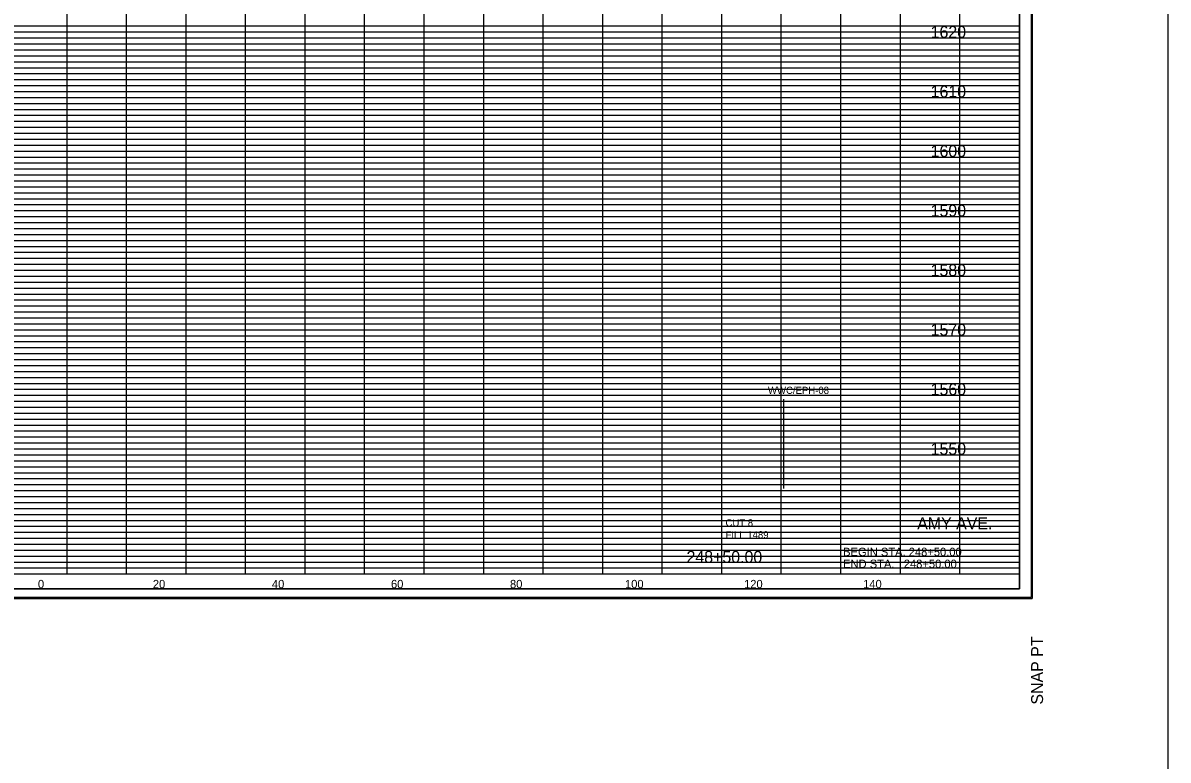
# Model space of a CAD drawing. Extents: x 955 to 1375, y 1248 to 3657.
# Drawn here: x 1152.6 to 1345, y 2858.7 to 2982.5 of the extents above; entities that cross this region are included whole.
import ezdxf

# ---------------------------------------------------------------- set-up
doc = ezdxf.new("R2010")
doc.units = 0
for name, color, linetype in [('DESIGN - SHEET - Corner Text', 7, 'Continuous'), ('DESIGN - SHEET - Light Grid', 7, 'Continuous'), ('DESIGN - SHEET - Linework', 7, 'Continuous'), ('DESIGN - SHEET - Plot Shape', 7, 'Continuous'), ('DESIGN - TYPICAL - Text', 7, 'Continuous'), ('DESIGN - UTILITIES - Cable (Overhead) with Text', 7, 'Continuous'), ('SURVEY - NON-TRANSPORTATION - Features', 7, 'Continuous'), ('SURVEY - NON-TRANSPORTATION - Features Text', 7, 'Continuous')]:
    doc.layers.add(name, color=color, linetype=linetype)

# ---------------------------------------------------------------- blocks, each defined once
blk = doc.blocks.new('XSTSHT')
at = {"layer": 'DESIGN - SHEET - Light Grid'}
for p, q in [((8, 9.2), (16, 9.2)), ((8, 9.1), (16, 9.1)), ((16, 9.2), (24, 9.2)), ((16, 9.1), (24, 9.1)), ((24, 9.2), (32, 9.2)), ((24, 9.1), (32, 9.1)), ((8, 8.9), (16, 8.9)), ((16, 8.9), (24, 8.9)), ((24, 8.9), (32, 8.9)), ((8, 8.8), (16, 8.8)), ((8, 8.7), (16, 8.7)), ((16, 8.8), (24, 8.8)), ((16, 8.7), (24, 8.7)), ((24, 8.8), (32, 8.8)), ((24, 8.7), (32, 8.7)), ((8, 8.6), (16, 8.6)), ((8, 8.5), (16, 8.5)), ((16, 8.6), (24, 8.6)), ((16, 8.5), (24, 8.5)), ((24, 8.6), (32, 8.6)), ((24, 8.5), (32, 8.5)), ((8, 8.4), (16, 8.4)), ((8, 8.3), (16, 8.3)), ((16, 8.4), (24, 8.4)), ((16, 8.3), (24, 8.3)), ((24, 8.4), (32, 8.4)), ((24, 8.3), (32, 8.3)), ((8, 8.2), (16, 8.2)), ((8, 8.1), (16, 8.1)), ((16, 8.2), (24, 8.2)), ((16, 8.1), (24, 8.1)), ((24, 8.2), (32, 8.2)), ((24, 8.1), (32, 8.1)), ((8, 7.9), (16, 7.9)), ((16, 7.9), (24, 7.9)), ((24, 7.9), (32, 7.9)), ((8, 7.8), (16, 7.8)), ((8, 7.7), (16, 7.7)), ((16, 7.8), (24, 7.8)), ((16, 7.7), (24, 7.7)), ((24, 7.8), (32, 7.8)), ((24, 7.7), (32, 7.7)), ((8, 7.6), (16, 7.6)), ((16, 7.6), (24, 7.6)), ((24, 7.6), (32, 7.6)), ((8, 7.5), (16, 7.5)), ((8, 7.4), (16, 7.4)), ((16, 7.5), (24, 7.5)), ((16, 7.4), (24, 7.4)), ((24, 7.5), (32, 7.5)), ((24, 7.4), (32, 7.4)), ((8, 7.3), (16, 7.3)), ((8, 7.2), (16, 7.2)), ((16, 7.3), (24, 7.3)), ((16, 7.2), (24, 7.2)), ((24, 7.3), (32, 7.3)), ((24, 7.2), (32, 7.2)), ((8, 7.1), (16, 7.1)), ((16, 7.1), (24, 7.1)), ((24, 7.1), (32, 7.1)), ((8, 6.9), (16, 6.9)), ((8, 6.8), (16, 6.8)), ((16, 6.9), (24, 6.9)), ((16, 6.8), (24, 6.8)), ((24, 6.9), (32, 6.9)), ((24, 6.8), (32, 6.8)), ((8, 6.7), (16, 6.7)), ((8, 6.6), (16, 6.6)), ((16, 6.7), (24, 6.7)), ((16, 6.6), (24, 6.6)), ((24, 6.7), (32, 6.7)), ((24, 6.6), (32, 6.6)), ((8, 6.5), (16, 6.5)), ((8, 6.4), (16, 6.4)), ((16, 6.5), (24, 6.5)), ((16, 6.4), (24, 6.4)), ((24, 6.5), (32, 6.5)), ((24, 6.4), (32, 6.4)), ((8, 6.3), (16, 6.3)), ((8, 6.2), (16, 6.2)), ((16, 6.3), (24, 6.3)), ((16, 6.2), (24, 6.2)), ((24, 6.3), (32, 6.3)), ((24, 6.2), (32, 6.2)), ((8, 6.1), (16, 6.1)), ((16, 6.1), (24, 6.1)), ((24, 6.1), (32, 6.1)), ((8, 5.9), (16, 5.9)), ((8, 5.8), (16, 5.8)), ((16, 5.9), (24, 5.9)), ((16, 5.8), (24, 5.8)), ((24, 5.9), (32, 5.9)), ((24, 5.8), (32, 5.8)), ((8, 5.7), (16, 5.7)), ((8, 5.6), (16, 5.6)), ((16, 5.7), (24, 5.7)), ((16, 5.6), (24, 5.6)), ((24, 5.7), (32, 5.7)), ((24, 5.6), (32, 5.6)), ((8, 5.5), (16, 5.5)), ((8, 5.4), (16, 5.4)), ((16, 5.5), (24, 5.5)), ((16, 5.4), (24, 5.4)), ((24, 5.5), (32, 5.5)), ((24, 5.4), (32, 5.4)), ((8, 5.3), (16, 5.3)), ((8, 5.2), (16, 5.2)), ((16, 5.3), (24, 5.3)), ((16, 5.2), (24, 5.2)), ((24, 5.3), (32, 5.3)), ((24, 5.2), (32, 5.2)), ((8, 5.1), (16, 5.1)), ((16, 5.1), (24, 5.1)), ((24, 5.1), (32, 5.1)), ((8, 4.9), (16, 4.9)), ((16, 4.9), (24, 4.9)), ((24, 4.9), (32, 4.9)), ((8, 4.8), (16, 4.8)), ((8, 4.7), (16, 4.7)), ((16, 4.8), (24, 4.8)), ((16, 4.7), (24, 4.7)), ((24, 4.8), (32, 4.8)), ((24, 4.7), (32, 4.7)), ((8, 4.6), (16, 4.6)), ((8, 4.5), (16, 4.5)), ((16, 4.6), (24, 4.6)), ((16, 4.5), (24, 4.5)), ((24, 4.6), (32, 4.6)), ((24, 4.5), (32, 4.5)), ((8, 4.4), (16, 4.4)), ((8, 4.3), (16, 4.3)), ((16, 4.4), (24, 4.4)), ((16, 4.3), (24, 4.3)), ((24, 4.4), (32, 4.4)), ((24, 4.3), (32, 4.3)), ((8, 4.2), (16, 4.2)), ((8, 4.1), (16, 4.1)), ((16, 4.2), (24, 4.2)), ((16, 4.1), (24, 4.1)), ((24, 4.2), (32, 4.2)), ((24, 4.1), (32, 4.1)), ((8, 3.9), (16, 3.9)), ((16, 3.9), (24, 3.9)), ((24, 3.9), (32, 3.9)), ((8, 3.8), (16, 3.8)), ((8, 3.7), (16, 3.7)), ((16, 3.8), (24, 3.8)), ((16, 3.7), (24, 3.7)), ((24, 3.8), (32, 3.8)), ((24, 3.7), (32, 3.7)), ((8, 3.6), (16, 3.6)), ((8, 3.5), (16, 3.5)), ((16, 3.6), (24, 3.6)), ((16, 3.5), (24, 3.5)), ((24, 3.6), (32, 3.6)), ((24, 3.5), (32, 3.5)), ((8, 3.4), (16, 3.4)), ((8, 3.3), (16, 3.3)), ((16, 3.4), (24, 3.4)), ((16, 3.3), (24, 3.3)), ((24, 3.4), (32, 3.4)), ((24, 3.3), (32, 3.3)), ((8, 3.2), (16, 3.2)), ((8, 3.1), (16, 3.1)), ((16, 3.2), (24, 3.2)), ((16, 3.1), (24, 3.1)), ((24, 3.2), (32, 3.2)), ((24, 3.1), (32, 3.1)), ((8, 2.9), (16, 2.9)), ((16, 2.9), (24, 2.9)), ((24, 2.9), (32, 2.9)), ((8, 2.8), (16, 2.8)), ((8, 2.7), (16, 2.7)), ((16, 2.8), (24, 2.8)), ((16, 2.7), (24, 2.7)), ((24, 2.8), (32, 2.8)), ((24, 2.7), (32, 2.7)), ((8, 2.6), (16, 2.6)), ((16, 2.6), (24, 2.6)), ((24, 2.6), (32, 2.6)), ((8, 2.5), (16, 2.5)), ((8, 2.4), (16, 2.4)), ((16, 2.5), (24, 2.5)), ((16, 2.4), (24, 2.4)), ((24, 2.5), (32, 2.5)), ((24, 2.4), (32, 2.4)), ((8, 2.3), (16, 2.3)), ((8, 2.2), (16, 2.2)), ((16, 2.3), (24, 2.3)), ((16, 2.2), (24, 2.2)), ((24, 2.3), (32, 2.3)), ((24, 2.2), (32, 2.2)), ((8, 2.1), (16, 2.1)), ((16, 2.1), (24, 2.1)), ((24, 2.1), (32, 2.1)), ((8, 1.9), (16, 1.9)), ((8, 1.8), (16, 1.8)), ((16, 1.9), (24, 1.9)), ((16, 1.8), (24, 1.8)), ((24, 1.9), (32, 1.9)), ((24, 1.8), (32, 1.8)), ((8, 1.7), (16, 1.7)), ((8, 1.6), (16, 1.6)), ((16, 1.7), (24, 1.7)), ((16, 1.6), (24, 1.6)), ((24, 1.7), (32, 1.7)), ((24, 1.6), (32, 1.6)), ((8, 1.5), (16, 1.5)), ((8, 1.4), (16, 1.4)), ((16, 1.5), (24, 1.5)), ((16, 1.4), (24, 1.4)), ((24, 1.5), (32, 1.5)), ((24, 1.4), (32, 1.4)), ((8, 1.3), (16, 1.3)), ((8, 1.2), (16, 1.2)), ((16, 1.3), (24, 1.3)), ((16, 1.2), (24, 1.2)), ((24, 1.3), (32, 1.3)), ((24, 1.2), (32, 1.2)), ((8, 1.1), (16, 1.1)), ((16, 1.1), (24, 1.1)), ((24, 1.1), (32, 1.1)), ((8, 0.9), (16, 0.9)), ((8, 0.8), (16, 0.8)), ((16, 0.9), (24, 0.9)), ((16, 0.8), (24, 0.8)), ((24, 0.9), (32, 0.9)), ((24, 0.8), (32, 0.8)), ((8, 0.7), (16, 0.7)), ((8, 0.6), (16, 0.6)), ((16, 0.7), (24, 0.7)), ((16, 0.6), (24, 0.6)), ((24, 0.7), (32, 0.7)), ((24, 0.6), (32, 0.6)), ((8, 0.5), (16, 0.5)), ((8, 0.4), (16, 0.4)), ((16, 0.5), (24, 0.5)), ((16, 0.4), (24, 0.4)), ((24, 0.5), (32, 0.5)), ((24, 0.4), (32, 0.4)), ((8, 0.3), (16, 0.3)), ((8, 0.2), (16, 0.2)), ((16, 0.3), (24, 0.3)), ((16, 0.2), (24, 0.2)), ((24, 0.3), (32, 0.3)), ((24, 0.2), (32, 0.2)), ((8, 0.1), (16, 0.1)), ((16, 0.1), (24, 0.1)), ((24, 0.1), (32, 0.1))]:
    blk.add_line(p, q, dxfattribs=at)
at = {"layer": 'DESIGN - SHEET - Linework'}
for p, q in [((32.217, 21.414), (32.217, -0.414)), ((16, 0), (16, 21)), ((17, 0), (17, 21)), ((18, 0), (18, 21)), ((19, 0), (19, 21)), ((20, 0), (20, 21)), ((21, 0), (21, 21)), ((22, 0), (22, 21)), ((23, 0), (23, 21)), ((24, 0), (24, 21)), ((25, 0), (25, 21)), ((26, 0), (26, 21)), ((27, 0), (27, 21)), ((28, 0), (28, 20)), ((29, 0), (29, 20)), ((30, 0), (30, 20)), ((31, 0), (31, 20)), ((0, 9), (32, 9)), ((0, 8), (32, 8)), ((0, 7), (32, 7)), ((0, 6), (32, 6)), ((0, 5), (32, 5)), ((0, 4), (32, 4)), ((0, 3), (32, 3)), ((0, 2), (32, 2)), ((0, 1), (32, 1)), ((-1.823, -0.414), (32.217, -0.414))]:
    blk.add_line(p, q, dxfattribs=at)
blk.add_lwpolyline([(0, 21), (0, 0), (32, 0), (32, 21), (0, 21)], dxfattribs=at)
at = {"layer": 'DESIGN - SHEET - Plot Shape'}
for points in [[(-1.803, 21.394), (32.197, 21.394), (32.197, -0.394), (-1.803, -0.394)], [(-0.85, 21), (32, 21), (32, -0.25), (-0.85, -0.25)]]:
    blk.add_lwpolyline(points, close=True, dxfattribs=at)
at = {"layer": 'DESIGN - SHEET - Corner Text'}
blk.add_text('SNAP PT  ', height=0.2, rotation=90, dxfattribs=at).set_placement((32.397, -2.194))

msp = doc.modelspace()

# ---------------------------------------------------------------- linework, layer by layer
at = {"layer": 'DESIGN - SHEET - Plot Shape'}
msp.add_lwpolyline([(991.5, 2887.5), (1320, 2887.5), (1320, 3100), (991.5, 3100)], close=True, dxfattribs=at)
at = {"layer": 'SURVEY - NON-TRANSPORTATION - Features'}
msp.add_line((1280.4, 2904.36), (1280.4, 2919.36), dxfattribs=at)
at = {"layer": 'SURVEY - NON-TRANSPORTATION - Features Text'}
msp.add_lwpolyline([(955.41, 1505.76), (1344.98, 1505.76), (1344.98, 3398.01), (955.41, 3398.01)], close=True, dxfattribs=at)

# ---------------------------------------------------------------- block references
at = {"layer": 'DESIGN - UTILITIES - Cable (Overhead) with Text', "xscale": 10, "yscale": 10}
msp.add_blockref('XSTSHT', (1000, 2890), dxfattribs=at)

# ---------------------------------------------------------------- texts
at = {"layer": 'DESIGN - SHEET - Corner Text'}
for s, height, p in [('AMY AVE.', 2, (1302.83, 2897.5)), ('BEGIN STA. 248+50.00', 1.4, (1290.38, 2893)), ('END STA.   248+50.00', 1.4, (1290.38, 2891))]:
    msp.add_text(s, height=height, dxfattribs=at).set_placement(p)
at = {"layer": 'DESIGN - TYPICAL - Text'}
for s, height, p in [('     1620     ', 2, (1301.37, 2980)), ('     1610     ', 2, (1301.37, 2970)), ('     1600     ', 2, (1301.37, 2960)), ('     1590     ', 2, (1301.37, 2950)), ('     1580     ', 2, (1301.37, 2940)), ('     1570     ', 2, (1301.37, 2930)), ('     1560     ', 2, (1301.37, 2920)), ('     1550     ', 2, (1301.37, 2910)), ('CUT 8', 1.2, (1270.63, 2897.98)), ('FILL 1489', 1.2, (1270.63, 2895.98)), ('     248+50.00     ', 2, (1260.36, 2891.86)), ('     0     ', 1.4, (1152.51, 2887.6)), ('     0     ', 1.4, (1152.51, 2887.6)), ('     20     ', 1.4, (1171.82, 2887.6)), ('     40     ', 1.4, (1191.82, 2887.6)), ('     60     ', 1.4, (1211.82, 2887.6)), ('     80     ', 1.4, (1231.82, 2887.6)), ('     100     ', 1.4, (1251.14, 2887.6)), ('     120     ', 1.4, (1271.14, 2887.6)), ('     140     ', 1.4, (1291.14, 2887.6))]:
    msp.add_text(s, height=height, dxfattribs=at).set_placement(p)
at = {"layer": 'SURVEY - NON-TRANSPORTATION - Features'}
msp.add_text('WWC/EPH-08', height=1.2, dxfattribs=at).set_placement((1277.76, 2920.23))

doc.saveas('drawing.dxf')
